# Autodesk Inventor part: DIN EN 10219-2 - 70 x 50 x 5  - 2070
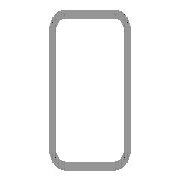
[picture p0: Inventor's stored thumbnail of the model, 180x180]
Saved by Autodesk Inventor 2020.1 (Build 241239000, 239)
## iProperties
Created: 2019-01
Part Number: DIN EN 10219-2 - 70 x 50 x 5  - 2070
Material: Stahl, weich
Description: Kaltgeformte, geschweißte Baustahl-Hohlprofile aus unlegiertem Feinkorn-Baustahl
Document SubType Name: Modeling
Standard: DIN
Designer: lutzd
Standard Revision: 2006-07
Standards Organization: DIN
Language: de-DE
Size Designation: 70 x 50 x 5
Categories: <MemberInstance><Categories><Category DisplayName="Profile" InternalName="089c4875-fa83-4c05-b084-43b9cc11f5ed" Mnemonic="GRDR"><CategoryParameter DisplayName="
Stock Number: 70 x 50 x 5
Mass: 16814.7 g
Surface Area: 8599.14 cm^2
Volume: 2142 cm^3
Density: 7.85 g/cm^3
Appearance: Halbpoliert
_CCFamilyMember: 17
_CCFamilyDisplayName: DIN EN 10219-2 (Rechteckiges Hohlprofil - Kaltgeformt) - Kaltgeformte, geschweißte Baustahl-Hohlprofile aus unlegiertem Feinkorn-Baustahl
_FrameMemberDoc: Frame Member File
_Version: 15.0.0
_GetPNFromCC: 1
G_L: 2070,000 mm
G_W: 50,000 mm
G_H: 70,000 mm
DocNumber: ADSK-014134
Folder: .
Dimensions: 50x70x2070 mm
Mass: 16,815 kg
+213A9B0C-C5E1-4A2F-BE09-57F5AEF2BA8C+SCHNITTDETAIL1: Schnittwinkel 90,00 grd
+3E7C2AFE-1FC6-4799-8E7C-C5A2F2184E34+SCHNITTDETAIL2: Schnittwinkel 90,00 grd
IsCustomPart: 1
Title: Profil-Bauteil
Author: lutzd
Revision Number: -
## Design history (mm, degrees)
node "Startebene"
node "Endebene"
sketch "Skizze"
  geometry: L1 (-25, -25)-(-25, 25); L2 (-15, 35)-(15, 35); L3 (25, 25)-(25, -25); L4 (15, -35)-(-15, -35); L5 (-15, 30)-(15, 30); L6 (20, 25)-(20, -25); L7 (15, -30)-(-15, -30); L8 (-20, -25)-(-20, 25); L9 (0, 51.899)-(0, -51.899) reference; L10 (-37.899, 0)-(37.899, 0) reference; A1 r 10 centre (-15, -25) between (-25, -25) and (-15, -35); A2 r 10 centre (-15, 25) between (-15, 35) and (-25, 25); A3 r 10 centre (15, 25) between (25, 25) and (15, 35); A4 r 10 centre (15, -25) between (15, -35) and (25, -25); A5 r 5 centre (-15, 25) between (-15, 30) and (-20, 25); A6 r 5 centre (15, 25) between (20, 25) and (15, 30); A7 r 5 centre (15, -25) between (15, -30) and (20, -25); A8 r 5 centre (-15, -25) between (-20, -25) and (-15, -30)
  constraints: 16 end point, 16 point on circle, 8 centre point, 8 tangent, 4 parallel, 3 equal radius, 2 perpendicular, 7 other
  dimensions: "d7" = 10 radius of A1 (= G_IR); "d10" = 70 distance between parallel lines of L2 L4 (= G_H); "d11" = 50 distance between parallel lines of L1 L3 (= G_W); "d12" = 5 distance between parallel lines of L3 L6 (= G_T); "d15" = 35 distance between parallel lines of L2 L10 (= 0.5 x d10); "d16" = 25 distance between parallel lines of L9 L3 (= 0.5 x d11)
extrude "Körper" new body sketch "Skizze" stored distance "d3" = 2070 (= G_L); taper "d4" = 0 deg
node "Driven Length"
  sketch "Sketch3"
    geometry: L1 (0, 0)-(10, 0) reference
    constraints: 2 end point, 1 horizontal
  workplane "Work Plane3"
  sketch "Sketch4"
    geometry: L1 (-2, 50)-(12, 50) reference; L2 (-2, 2120)-(12, 2120) reference
    dimensions: "d18" = 2070 distance between parallel lines of L1 L2 (derived)
workplane "Arbeitsebene4"
feature "Trennen1"
workplane "Arbeitsebene5"
feature "Trennen2"
sketch "Skizze5"
  geometry: L1 (1902.5, -6)-(1902.5, -44); L2 (117.5, -6)-(117.5, -44); L3 (547, -6)-(547, -44); L4 (1010, -6)-(1010, -44); L5 (1533, -6)-(1533, -44); 22 further points
  constraints: 17 horizontal alignment, 10 end point, 5 coincident, 5 midpoint, 5 vertical, 10 other
  dimensions: "d19" = 38 distance of L1.start L1.end; "d20" = 167.5 dimension on L1; "d24" = 369.5 distance between parallel lines of L1 L5; "d25" = 523 distance between parallel lines of L4 L5; "d26" = 463 distance between parallel lines of L4 L3; "d28" = 429.5 distance between parallel lines of L2 L3
hole "Bohrung1" sketch "Skizze5" at (1902.5, -6), (1902.5, -44), (117.5, -6), (117.5, -44), (547, -6), (547, -44), (1010, -6), (1010, -44), (1533, -6), (1533, -44) diameter "d29" = 6.647; stored, may be unused: countersink angle "d33" = 82 deg, drill point angle "d35" = 118 deg; dims "d30" = 16, "d31" = 15, "d32" = 9, "d34" = 22.2
body "Solid1"
other parameters: "G_W" = 50 [user parameter; used in 1 equation term], "G_H" = 70 [user parameter; used in 1 equation term], "G_T" = 5 [user parameter; used in 1 equation term], "G_IR" = 10 [user parameter; used in 1 equation term], "G_L" = 2070 (= d18) [user parameter; used in 1 equation term], "d17" = 90 deg
